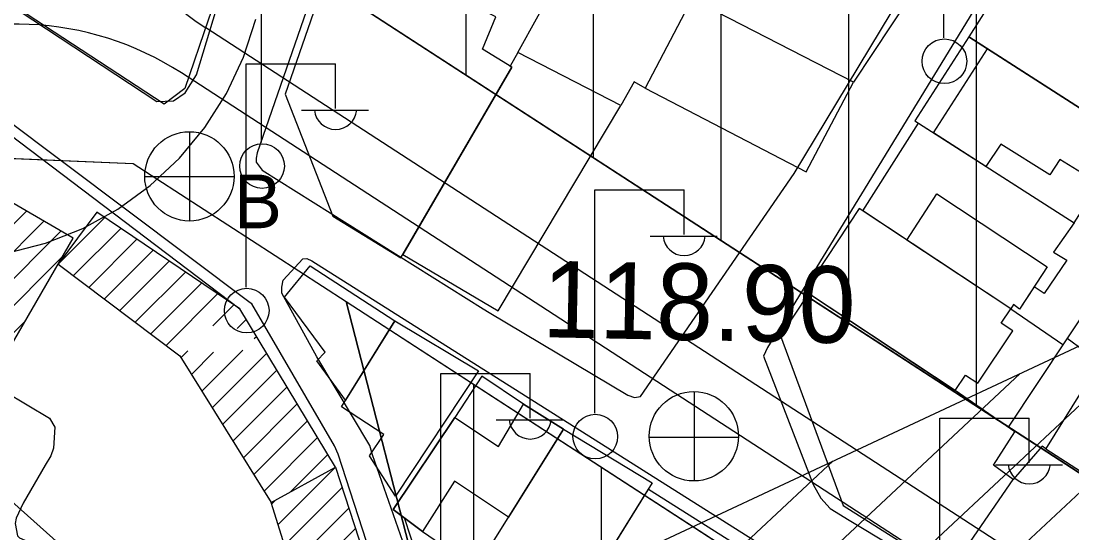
# Model space of a CAD drawing. Extents: x 417997 to 421451, y 4451742 to 4455216.
# Drawn here: x 419296 to 419378.3, y 4452649.9 to 4452690.1 of the extents above; entities that cross this region are included whole.
import ezdxf

# ---------------------------------------------------------------- set-up
doc = ezdxf.new("R2010")
doc.units = 0
for name, color, linetype in [('ADA', 7, 'Continuous'), ('ADAKENARI', 7, 'Continuous'), ('B_Betonzemin', 7, 'Continuous'), ('B_Mesken', 7, 'Continuous'), ('B_Resmi', 7, 'Continuous'), ('B_Tarama', 7, 'Continuous'), ('B_Teras', 7, 'Continuous'), ('KALDIRIM', 7, 'Continuous'), ('KD_KAV_25', 7, 'Continuous'), ('PL_KON_MEV_350', 7, 'Continuous'), ('PL_TA_K_TRAFO', 7, 'Continuous'), ('S_Elektrik_Diregi', 7, 'Continuous'), ('S_Pilon', 7, 'Continuous'), ('S_Rogar_Kapagi', 7, 'Continuous'), ('S_Rogar_Kapagi_Buski', 7, 'Continuous'), ('Sinir_Duvar_tek_tarafa_ait', 7, 'Continuous'), ('TA_ENH_KORUMA', 7, 'Continuous'), ('TA_ENH_TARAMA', 7, 'Continuous'), ('TR_ORTAYOGUNKONUT', 7, 'Continuous'), ('Y_Yol_Kotu', 7, 'Continuous'), ('Yol_Sose', 7, 'Continuous')]:
    doc.layers.add(name, color=color, linetype=linetype)

msp = doc.modelspace()

# ---------------------------------------------------------------- linework, layer by layer
at = {"layer": 'ADA'}
msp.add_line((419327.559, 4452644.431), (419321.464, 4452668.08), dxfattribs=at)
msp.add_line((419327.559, 4452644.431), (419321.464, 4452668.08), dxfattribs=at)
at = {"layer": 'ADAKENARI'}
for p, q in [((419431.327, 4452620.662), (419314.743, 4452696.278)), ((419431.327, 4452620.662), (419314.743, 4452696.278)), ((419287.562, 4452679.629), (419304.767, 4452678.91)), ((419287.562, 4452679.629), (419304.767, 4452678.91)), ((419304.767, 4452678.91), (419321.464, 4452668.08)), ((419304.767, 4452678.91), (419321.464, 4452668.08)), ((419321.464, 4452668.08), (419368.009, 4452637.891)), ((419321.464, 4452668.08), (419368.009, 4452637.891))]:
    msp.add_line(p, q, dxfattribs=at)
at = {"layer": 'B_Betonzemin'}
for points in [[(419294.715, 4452661.031), (419298.212, 4452658.948)], [(419298.212, 4452658.948), (419298.623, 4452658.229), (419298.516, 4452656.605), (419298.306, 4452655.988), (419297.875, 4452655.269), (419296.15, 4452652.287), (419295.597, 4452651.112), (419295.528, 4452650.68), (419295.687, 4452649.725), (419295.844, 4452649.557), (419298.109, 4452648.576)]]:
    msp.add_lwpolyline(points, dxfattribs=at)
at = {"layer": 'B_Mesken'}
for points in [[(419310.672, 4452690.201), (419308.808, 4452684.791), (419307.183, 4452683.554), (419294.947, 4452691.557), (419298.461, 4452700.809), (419305.921, 4452698.321), (419312.796, 4452696.231)], [(419348.545, 4452691.806), (419352.242, 4452699.157), (419364.589, 4452692.584), (419365.682, 4452692.033), (419361.232, 4452685.275)], [(419325.745, 4452671.498), (419334.444, 4452686.452), (419332.152, 4452687.857), (419333.179, 4452690.391), (419320.915, 4452696.559), (419316.68, 4452684.328), (419320.423, 4452674.77)], [(419374.541, 4452695.566), (419370.253, 4452688.836), (419371.726, 4452687.892), (419382.803, 4452680.793), (419386.84, 4452687.735)], [(419344.905, 4452684.804), (419357.512, 4452678.254), (419361.232, 4452685.275), (419348.545, 4452691.806)], [(419366.027, 4452682.242), (419378.515, 4452674.24), (419379.314, 4452675.487), (419380.4, 4452674.79), (419383.061, 4452678.942), (419382.037, 4452679.598), (419382.803, 4452680.793), (419370.253, 4452688.836)], [(419325.909, 4452671.78), (419333.37, 4452667.363), (419342.993, 4452683.434), (419334.916, 4452687.586), (419334.302, 4452686.539), (419334.444, 4452686.452)], [(419361.947, 4452675.198), (419366.307, 4452682.063), (419378.515, 4452674.24), (419376.905, 4452671.966), (419377.95, 4452671.326), (419376.176, 4452668.724), (419375.381, 4452669.232), (419374.244, 4452667.5), (419373.772, 4452667.851), (419373.556, 4452667.515)], [(419357.404, 4452668.913), (419369.201, 4452661.105), (419370.006, 4452662.321), (419370.98, 4452661.677), (419373.702, 4452665.791), (419372.807, 4452666.384), (419373.556, 4452667.515), (419361.681, 4452675.374)], [(419321.41, 4452660.353), (419319.157, 4452663.437), (419319.816, 4452664.114), (419316.616, 4452668.424), (419318.639, 4452670.884), (419325.269, 4452666.577)], [(419357.703, 4452668.715), (419355.493, 4452665.393), (419360.422, 4452652.107), (419368.727, 4452646.864), (419373.744, 4452654.142), (419372.207, 4452655.276), (419373.88, 4452657.88), (419369.201, 4452661.105)], [(419323.287, 4452655.992), (419324.402, 4452657.663), (419321.082, 4452659.823), (419325.269, 4452666.577), (419331.819, 4452662.665), (419325.336, 4452652.84)], [(419380.433, 4452663.147), (419392.753, 4452655.005), (419390.093, 4452650.625), (419386.074, 4452650.215), (419376.292, 4452656.515)], [(419327.436, 4452650.077), (419331.662, 4452647.154), (419338.503, 4452658.093), (419335.368, 4452660.055), (419332.094, 4452662.238), (419329.978, 4452659.008), (419325.156, 4452651.781)], [(419331.545, 4452646.966), (419338.503, 4452658.093), (419345.455, 4452653.866), (419338.496, 4452642.647)], [(419345.153, 4452653.379), (419351.81, 4452649.185), (419345.223, 4452638.488), (419344.697, 4452637.649), (419338.234, 4452642.101), (419338.496, 4452642.647)]]:
    msp.add_lwpolyline(points, close=True, dxfattribs=at)
at = {"layer": 'B_Resmi'}
for points in [[(419284.635, 4452646.403), (419300.054, 4452673.043), (419289.785, 4452679.003), (419274.298, 4452652.295)], [(419298.886, 4452671.026), (419308.416, 4452663.832), (419315.589, 4452652.345), (419320.626, 4452655.105), (419313.115, 4452667.503), (419301.925, 4452675.089)], [(419320.626, 4452655.105), (419324.99, 4452641.706), (419318.71, 4452639.294), (419316.389, 4452645.46), (419317.573, 4452645.979), (419315.589, 4452652.345)]]:
    msp.add_lwpolyline(points, close=True, dxfattribs=at)
at = {"layer": 'B_Tarama'}
for p, q in [((419285.286, 4452664.025), (419296.416, 4452675.154)), ((419287.329, 4452663.946), (419297.758, 4452674.375)), ((419298.886, 4452671.026), (419302.535, 4452674.675)), ((419289.514, 4452664.01), (419299.101, 4452673.596)), ((419300.095, 4452670.114), (419303.8, 4452673.818)), ((419301.304, 4452669.201), (419305.064, 4452672.961)), ((419302.513, 4452668.289), (419306.328, 4452672.104)), ((419277.879, 4452650.254), (419299.208, 4452671.583)), ((419303.721, 4452667.376), (419307.592, 4452671.247)), ((419304.93, 4452666.463), (419308.857, 4452670.39)), ((419306.139, 4452665.551), (419310.121, 4452669.533)), ((419307.348, 4452664.638), (419311.385, 4452668.676)), ((419311.017, 4452666.187), (419312.649, 4452667.819)), ((419312.919, 4452665.967), (419313.62, 4452666.668)), ((419279.23, 4452649.484), (419296.294, 4452666.547)), ((419314.256, 4452665.183), (419314.421, 4452665.347)), ((419308.511, 4452663.68), (419309.054, 4452664.223)), ((419310.142, 4452661.069), (419313.356, 4452664.283)), ((419309.326, 4452662.374), (419311.068, 4452664.116)), ((419310.957, 4452659.763), (419315.221, 4452664.026)), ((419311.773, 4452658.457), (419316.021, 4452662.705)), ((419312.588, 4452657.151), (419316.822, 4452661.384)), ((419313.404, 4452655.845), (419317.622, 4452660.063)), ((419314.219, 4452654.539), (419318.422, 4452658.742)), ((419315.035, 4452653.233), (419319.223, 4452657.421)), ((419317.09, 4452653.167), (419320.023, 4452656.1)), ((419316.13, 4452650.61), (419320.626, 4452655.105)), ((419316.634, 4452648.992), (419321.147, 4452653.505)), ((419315.626, 4452652.227), (419315.932, 4452652.533)), ((419317.138, 4452647.375), (419321.668, 4452651.905)), ((419316.65, 4452644.766), (419322.189, 4452650.305))]:
    msp.add_line(p, q, dxfattribs=at)
at = {"layer": 'B_Teras'}
for points in [[(419367.489, 4452681.305), (419371.726, 4452687.892), (419382.803, 4452680.793), (419382.037, 4452679.598), (419380.452, 4452677.329), (419377.405, 4452679.202), (419376.622, 4452678.016), (419372.778, 4452680.425), (419371.588, 4452678.679)], [(419365.411, 4452672.906), (419367.764, 4452676.533), (419376.411, 4452670.799), (419374.244, 4452667.5), (419373.772, 4452667.851), (419373.556, 4452667.515)], [(419334.185, 4452651.188), (419329.962, 4452654.007), (419327.436, 4452650.077), (419325.156, 4452651.781), (419329.978, 4452659.008), (419333.411, 4452656.734), (419335.368, 4452660.055), (419338.503, 4452658.093)]]:
    msp.add_lwpolyline(points, close=True, dxfattribs=at)
at = {"layer": 'KALDIRIM'}
for p, q in [((419426.973, 4452613.95), (419310.461, 4452689.52)), ((419426.973, 4452613.95), (419310.461, 4452689.52)), ((419368.941, 4452646.822), (419308.547, 4452685.993)), ((419368.941, 4452646.822), (419308.547, 4452685.993))]:
    msp.add_line(p, q, dxfattribs=at)
for centre, radius, start, end in [((419320.932, 4452705.664), 19.243, 153.24723, 237.03266), ((419320.932, 4452705.664), 19.243, 153.24723, 237.03266), ((419295.612, 4452666.05), 23.771, 57.03266, 118.17859), ((419295.612, 4452666.05), 23.771, 57.03266, 118.17859)]:
    msp.add_arc(centre, radius, start, end, dxfattribs=at)
at = {"layer": 'KD_KAV_25'}
for p, q in [((419313.412, 4452687.224), (419314.383, 4452690.21)), ((419313.412, 4452687.224), (419314.383, 4452690.21)), ((419312.076, 4452684.384), (419313.412, 4452687.224)), ((419312.076, 4452684.384), (419313.412, 4452687.224)), ((419310.393, 4452681.733), (419312.076, 4452684.384)), ((419310.393, 4452681.733), (419312.076, 4452684.384)), ((419308.392, 4452679.314), (419310.393, 4452681.733)), ((419308.392, 4452679.314), (419310.393, 4452681.733)), ((419306.104, 4452677.165), (419308.392, 4452679.314)), ((419306.104, 4452677.165), (419308.392, 4452679.314)), ((419303.564, 4452675.319), (419306.104, 4452677.165)), ((419303.564, 4452675.319), (419306.104, 4452677.165)), ((419300.812, 4452673.807), (419303.564, 4452675.319)), ((419300.812, 4452673.807), (419303.564, 4452675.319)), ((419297.893, 4452672.651), (419300.812, 4452673.807)), ((419297.893, 4452672.651), (419300.812, 4452673.807)), ((419294.853, 4452671.87), (419297.893, 4452672.651)), ((419294.853, 4452671.87), (419297.893, 4452672.651))]:
    msp.add_line(p, q, dxfattribs=at)
at = {"layer": 'PL_KON_MEV_350'}
msp.add_lwpolyline([(419466.594, 4452606.411), (419460.376, 4452607.831), (419454.262, 4452609.644), (419448.276, 4452611.844), (419442.443, 4452614.421), (419436.785, 4452617.364), (419431.327, 4452620.662), (419314.743, 4452696.278), (419310.855, 4452710.649), (419356.122, 4452800.447), (419357.685, 4452803.629), (419359.18, 4452806.842), (419360.609, 4452810.086), (419361.969, 4452813.358), (419363.261, 4452816.659), (419364.484, 4452819.985), (419365.637, 4452823.337), (419366.72, 4452826.711), (419382.894, 4452878.974)], dxfattribs=at)
msp.add_lwpolyline([(419368.009, 4452637.891), (419371.522, 4452623.719), (419356.186, 4452596.266), (419335.23, 4452614.666), (419327.559, 4452644.431), (419321.464, 4452668.08)], close=True, dxfattribs=at)
at = {"layer": 'PL_TA_K_TRAFO'}
msp.add_lwpolyline([(419184.085, 4452580.034), (419241.764, 4452647.385), (419244.86, 4452650.834), (419248.112, 4452654.136), (419251.513, 4452657.284), (419255.056, 4452660.271), (419258.734, 4452663.091), (419262.539, 4452665.737), (419266.462, 4452668.204), (419270.496, 4452670.487), (419287.562, 4452679.629), (419304.767, 4452678.91), (419321.464, 4452668.08), (419327.559, 4452644.431), (419257.467, 4452508.431)], dxfattribs=at)
msp.add_lwpolyline([(419184.085, 4452580.034), (419241.764, 4452647.385), (419244.86, 4452650.834), (419248.112, 4452654.136), (419251.513, 4452657.284), (419255.056, 4452660.271), (419258.734, 4452663.091), (419262.539, 4452665.737), (419266.462, 4452668.204), (419270.496, 4452670.487), (419287.562, 4452679.629), (419304.767, 4452678.91), (419321.464, 4452668.08), (419327.559, 4452644.431), (419257.467, 4452508.431)], dxfattribs=at)
at = {"layer": 'S_Elektrik_Diregi'}
for p, q in [((419368.316, 4452688.751), (419368.316, 4452706.251)), ((419314.832, 4452680.54), (419314.832, 4452698.04)), ((419313.631, 4452669.212), (419313.631, 4452686.712)), ((419313.631, 4452686.712), (419320.631, 4452686.712)), ((419320.631, 4452683.212), (419320.631, 4452686.712)), ((419317.971, 4452683.072), (419323.221, 4452683.072)), ((419340.946, 4452659.336), (419340.946, 4452676.836)), ((419340.946, 4452676.836), (419347.946, 4452676.836)), ((419347.946, 4452673.336), (419347.946, 4452676.836)), ((419345.286, 4452673.196), (419350.536, 4452673.196)), ((419328.886, 4452644.955), (419328.886, 4452662.455)), ((419328.886, 4452662.455), (419335.886, 4452662.455)), ((419335.886, 4452658.955), (419335.886, 4452662.455)), ((419333.226, 4452658.815), (419338.476, 4452658.815)), ((419368.003, 4452641.441), (419368.003, 4452658.941)), ((419368.003, 4452658.941), (419375.003, 4452658.941)), ((419375.003, 4452655.441), (419375.003, 4452658.941)), ((419372.343, 4452655.301), (419377.593, 4452655.301))]:
    msp.add_line(p, q, dxfattribs=at)
for centre in [(419368.352, 4452686.916), (419314.868, 4452678.704), (419313.667, 4452667.376), (419340.982, 4452657.5)]:
    msp.add_circle(centre, 1.75, dxfattribs=at)
for centre in [(419320.631, 4452683.225), (419347.947, 4452673.349), (419335.887, 4452658.968), (419375.003, 4452655.454)]:
    msp.add_arc(centre, 1.658, 184.83843, 355.14641, dxfattribs=at)
at = {"layer": 'S_Pilon'}
msp.add_lwpolyline([(419292.982, 4452654.435), (419303.429, 4452645.115), (419294.108, 4452634.668), (419283.662, 4452643.988), (419292.982, 4452654.435)], dxfattribs=at)
at = {"layer": 'S_Rogar_Kapagi'}
for p, q in [((419348.763, 4452653.999), (419348.763, 4452660.999)), ((419345.193, 4452657.464), (419352.193, 4452657.464))]:
    msp.add_line(p, q, dxfattribs=at)
msp.add_circle((419348.71, 4452657.527), 3.5, dxfattribs=at)
at = {"layer": 'S_Rogar_Kapagi_Buski'}
for p, q in [((419309.174, 4452681.395), (419309.174, 4452674.395)), ((419305.674, 4452677.895), (419312.674, 4452677.895))]:
    msp.add_line(p, q, dxfattribs=at)
msp.add_circle((419309.174, 4452677.895), 3.5, dxfattribs=at)
at = {"layer": 'Sinir_Duvar_tek_tarafa_ait'}
for points in [[(419334.916, 4452687.586), (419339.69, 4452696.257)], [(419248.817, 4452658.082), (419257.897, 4452670.896), (419270.556, 4452685.294), (419284.388, 4452689.26), (419313.115, 4452667.503)], [(419344.905, 4452684.804), (419344.039, 4452685.302), (419342.993, 4452683.434)], [(419382.491, 4452672.011), (419373.354, 4452658.243)], [(419373.556, 4452667.515), (419377.644, 4452664.707)], [(419380.523, 4452663.298), (419377.972, 4452665.201)], [(419376.31, 4452656.544), (419376.015, 4452656.748), (419373.744, 4452654.142)], [(419331.263, 4452639.985), (419331.332, 4452640.099), (419327.53, 4452646.597), (419326.019, 4452651.136)]]:
    msp.add_lwpolyline(points, dxfattribs=at)
at = {"layer": 'TA_ENH_KORUMA'}
msp.add_line((419287.522, 4452621.877), (419466.015, 4452705.355), dxfattribs=at)
msp.add_line((419287.522, 4452621.877), (419466.015, 4452705.355), dxfattribs=at)
at = {"layer": 'TA_ENH_TARAMA'}
for p, q in [((419323.232, 4452601.054), (419403.6, 4452676.165)), ((419323.232, 4452601.054), (419403.6, 4452676.165)), ((419318.722, 4452603.684), (419388.941, 4452669.309)), ((419318.722, 4452603.684), (419388.941, 4452669.309)), ((419314.212, 4452606.314), (419374.282, 4452662.453)), ((419314.212, 4452606.314), (419374.282, 4452662.453)), ((419309.702, 4452608.943), (419359.623, 4452655.597)), ((419309.702, 4452608.943), (419359.623, 4452655.597))]:
    msp.add_line(p, q, dxfattribs=at)
at = {"layer": 'TR_ORTAYOGUNKONUT'}
for p, q in [((419360.855, 4452666.37), (419360.855, 4452810.677)), ((419360.855, 4452666.37), (419360.855, 4452810.677)), ((419350.855, 4452672.856), (419350.855, 4452789.998)), ((419350.855, 4452672.856), (419350.855, 4452789.998)), ((419340.855, 4452679.342), (419340.855, 4452770.161)), ((419340.855, 4452679.342), (419340.855, 4452770.161)), ((419330.855, 4452685.828), (419330.855, 4452750.323)), ((419330.855, 4452685.828), (419330.855, 4452750.323)), ((419370.855, 4452659.884), (419370.855, 4452710.101)), ((419370.855, 4452659.884), (419370.855, 4452710.101)), ((419331.464, 4452629.28), (419331.464, 4452661.594)), ((419331.464, 4452629.28), (419331.464, 4452661.594)), ((419341.464, 4452609.193), (419341.464, 4452655.108)), ((419341.464, 4452609.193), (419341.464, 4452655.108))]:
    msp.add_line(p, q, dxfattribs=at)
at = {"layer": 'Yol_Sose'}
for points in [[(419294.769, 4452691.564), (419306.627, 4452683.763), (419307.93, 4452683.811), (419308.853, 4452684.451), (419309.727, 4452685.839), (419318.123, 4452713.528), (419332.947, 4452758.654), (419349.23, 4452808.282), (419349.249, 4452808.804), (419348.99, 4452809.449), (419348.487, 4452809.798), (419347.513, 4452810.027), (419347.025, 4452809.802), (419345.836, 4452808.447), (419329.303, 4452777.908), (419315.631, 4452749.71), (419297.387, 4452707.564), (419294.756, 4452701.239), (419294.441, 4452700.579), (419293.943, 4452697.208), (419293.867, 4452695.365), (419293.983, 4452693.469), (419294.275, 4452692.39)], [(419332.661, 4452667.232), (419343.534, 4452660.75), (419344.057, 4452660.566), (419344.536, 4452660.633), (419356.582, 4452678.121), (419375.971, 4452710.24), (419387.612, 4452729.211), (419409.906, 4452764.808), (419410.159, 4452765.422), (419410.229, 4452766.106), (419409.845, 4452766.973), (419354.705, 4452799.226), (419354.546, 4452799.226), (419354.044, 4452799.114), (419353.746, 4452798.727), (419333.109, 4452733.5), (419314.492, 4452679.729), (419314.399, 4452679.319), (419314.399, 4452679.046), (419314.398, 4452679), (419314.875, 4452678.383), (419332.206, 4452667.506)], [(419360.887, 4452650.941), (419380.942, 4452638.898), (419382.445, 4452638.597), (419383.585, 4452638.89), (419384.247, 4452639.275), (419385.184, 4452640.137), (419420.552, 4452697.69), (419448.007, 4452740.63), (419448.169, 4452741.154), (419448.034, 4452741.747), (419415.549, 4452761.937), (419414.637, 4452762.259), (419414.202, 4452762.123), (419354.474, 4452664.493), (419354.175, 4452663.81), (419358.062, 4452653.748), (419358.651, 4452652.675), (419359.401, 4452651.875)]]:
    msp.add_lwpolyline(points, close=True, dxfattribs=at)
for points in [[(419314.611, 4452587.616), (419332, 4452621.408), (419332.206, 4452621.816), (419332.231, 4452622.317), (419326.218, 4452639.527), (419320.84, 4452656.122), (419320.546, 4452656.782), (419314.059, 4452667.901), (419313.923, 4452667.992), (419284.805, 4452689.834), (419284.351, 4452689.881), (419283.487, 4452689.93), (419270.47, 4452685.702), (419269.581, 4452685.092), (419256.847, 4452670.45), (419248.419, 4452658.544), (419239.004, 4452643.868), (419225.357, 4452628.161), (419213.215, 4452613.631), (419189.05, 4452586.571)], [(419353.645, 4452594.677), (419342.284, 4452609.651), (419337.886, 4452615.813), (419337.321, 4452616.93), (419328.453, 4452641.963), (419323.535, 4452656.075), (419323.31, 4452656.804), (419319.165, 4452663.74), (419316.426, 4452668.735), (419316.405, 4452669.214), (419316.52, 4452669.76), (419318.052, 4452671.418), (419318.371, 4452671.462), (419318.757, 4452671.279), (419376.962, 4452634.53), (419377.871, 4452633.73), (419378.187, 4452633.069), (419378.23, 4452632.158), (419376.8, 4452626.856), (419376.502, 4452626.242), (419364.548, 4452606.669), (419355.72, 4452595.331)]]:
    msp.add_lwpolyline(points, dxfattribs=at)

# ---------------------------------------------------------------- texts
at = {"layer": 'S_Rogar_Kapagi_Buski'}
msp.add_text('B', height=4.2, dxfattribs=at).set_placement((419312.674, 4452673.831))
at = {"layer": 'Y_Yol_Kotu'}
msp.add_text('118.90 ', height=6, rotation=358.87031, dxfattribs=at).set_placement((419336.789, 4452665.293))

doc.saveas('drawing.dxf')
